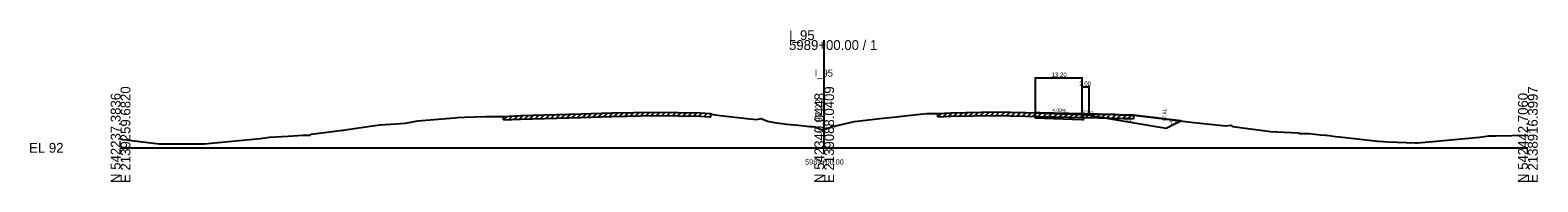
# Model space of a CAD drawing. Extents: x -12534 to 3403, y -1332 to 21983.
# Drawn here: x -25.7 to 402.8, y 17990.3 to 18033.5 of the extents above; entities that cross this region are included whole.
import ezdxf

# ---------------------------------------------------------------- set-up
doc = ezdxf.new("R2010")
doc.units = 0
for name, color, linetype in [('RD_GPK_XS_Cell', 7, 'Continuous'), ('RD_XD_TX_Width', 7, 'Continuous'), ('RD_XS_Base', 7, 'Continuous'), ('RD_XS_EarthShd', 7, 'Continuous'), ('RD_XS_EwShp', 7, 'Continuous'), ('RD_XS_ExGround', 7, 'Continuous'), ('RD_XS_ExPaveRet', 7, 'Continuous'), ('RD_XS_OSBase', 7, 'Continuous'), ('RD_XS_Pave', 7, 'Continuous'), ('RD_XS_TieSlope', 7, 'Continuous'), ('RD_XS_TX_Baseline', 7, 'Continuous'), ('RD_XS_TX_Elev_EX', 7, 'Continuous'), ('RD_XS_TX_Elev_PR', 7, 'Continuous'), ('RD_XS_TX_ShdSlope', 7, 'Continuous'), ('RD_XS_TX_Slope', 7, 'Continuous'), ('RD_XS_TX_Station', 7, 'Continuous')]:
    doc.layers.add(name, color=color, linetype=linetype)

msp = doc.modelspace()

# ---------------------------------------------------------------- linework, layer by layer
at = {"layer": 'RD_GPK_XS_Cell'}
for p, q in [((200, 18000), (200, 18030.63)), ((0, 18000), (200, 18000)), ((200, 18000), (400, 18000))]:
    msp.add_line(p, q, dxfattribs=at)
at = {"layer": 'RD_XD_TX_Width'}
for p, q in [((260, 18020.11), (260, 18010.16)), ((260, 18019.91), (273.2, 18019.91)), ((273.2, 18020.11), (273.2, 18009.63)), ((273.2, 18017.58), (273.2, 18009.63)), ((273.2, 18017.38), (275.2, 18017.38)), ((275.2, 18017.58), (275.2, 18009.47))]:
    msp.add_line(p, q, dxfattribs=at)
at = {"layer": 'RD_XS_Base'}
msp.add_line((260, 18008.56), (273.2, 18008.03), dxfattribs=at)
at = {"layer": 'RD_XS_EarthShd'}
msp.add_line((273.2, 18009.43), (275.2, 18009.27), dxfattribs=at)
at = {"layer": 'RD_XS_EwShp'}
msp.add_lwpolyline([(273.2, 18009.03), (273.2, 18009.43), (275.2, 18009.27), (297.2, 18005.61), (301.37, 18007.69), (297.29, 18008.18), (295.05, 18008.47), (294.33, 18008.54), (288.64, 18009.16), (287.91, 18009.27), (287.12, 18009.3), (286.84, 18009.33), (284.97, 18009.31), (282.59, 18009.43), (282.11, 18009.46), (265.41, 18009.82), (261.42, 18009.93), (260, 18009.96), (260, 18009.56), (260, 18008.56), (273.2, 18008.03), (273.7, 18008.01), (273.7, 18009.01)], close=True, dxfattribs=at)
at = {"layer": 'RD_XS_ExGround'}
msp.add_lwpolyline([(0, 18002.42), (10.99, 18001.15), (22.38, 18001.11), (23.19, 18001.1), (23.8, 18001.12), (39.73, 18002.62), (42.34, 18003.02), (47.63, 18003.35), (51.79, 18003.6), (53.86, 18003.6), (54.17, 18003.84), (63.19, 18004.97), (63.51, 18005.01), (64.49, 18005.16), (71.59, 18006.26), (73.83, 18006.56), (81.02, 18007.05), (84.49, 18007.67), (93.75, 18008.44), (95.02, 18008.55), (95.67, 18008.58), (97.75, 18008.67), (103.79, 18008.91), (107.63, 18008.91), (108.38, 18008.93), (108.85, 18008.94), (113.7, 18009.14), (130.84, 18009.65), (139.65, 18009.93), (152.01, 18010.16), (164.86, 18009.96), (167.33, 18009.77), (167.72, 18009.74), (168.08, 18009.53), (168.47, 18009.47), (170.39, 18009.23), (178.86, 18008.21), (180.79, 18008.02), (182.06, 18008.29), (183.26, 18007.83), (183.84, 18007.57), (185.86, 18007.23), (189.29, 18006.73), (192.69, 18006.39), (195.78, 18006.09), (196.54, 18006.08), (197.44, 18005.94), (199.01, 18005.21), (200, 18005.22), (201.6, 18005.82), (202.75, 18006.25), (202.76, 18006.08), (203.27, 18006.23), (208.47, 18007.49), (210.2, 18007.67), (215.84, 18008.29), (220.53, 18008.83), (222.91, 18009.1), (226.36, 18009.5), (229.16, 18009.73), (232.34, 18009.76), (235.95, 18009.99), (248.8, 18010.21), (261.42, 18009.93), (265.41, 18009.82), (282.11, 18009.46), (282.59, 18009.43), (284.97, 18009.31), (286.84, 18009.33), (287.12, 18009.3), (287.91, 18009.27), (288.64, 18009.16), (294.33, 18008.54), (295.05, 18008.47), (297.29, 18008.18), (305.07, 18007.24), (314.17, 18006.29), (315.54, 18006.45), (316.22, 18006.06), (318.85, 18005.69), (325.54, 18004.78), (326.88, 18004.66), (334.72, 18004.29), (335.31, 18004.07), (337.83, 18004.03), (341.11, 18003.64), (342.35, 18003.56), (342.91, 18003.59), (345.28, 18003.26), (346.47, 18003.11), (350.68, 18002.64), (357.39, 18001.86), (358.97, 18001.76), (360.25, 18001.69), (367.96, 18001.41), (368.65, 18001.39), (373.03, 18001.75), (386.21, 18003.02), (388.87, 18003.41), (391.03, 18003.4), (400, 18003.62)], dxfattribs=at)
at = {"layer": 'RD_XS_ExPaveRet'}
for p, q in [((108.85, 18007.94), (109.89, 18008.98)), ((108.85, 18007.94), (108.85, 18008.94)), ((108.85, 18007.94), (113.7, 18008.14)), ((110.35, 18008), (111.39, 18009.05)), ((111.85, 18008.07), (112.89, 18009.11)), ((113.35, 18008.13), (114.38, 18009.16)), ((113.7, 18008.14), (130.84, 18008.65)), ((114.85, 18008.18), (115.88, 18009.21)), ((116.35, 18008.22), (117.38, 18009.25)), ((117.85, 18008.27), (118.88, 18009.3)), ((119.35, 18008.31), (120.38, 18009.34)), ((120.85, 18008.35), (121.88, 18009.39)), ((122.35, 18008.4), (123.38, 18009.43)), ((123.85, 18008.44), (124.88, 18009.47)), ((125.35, 18008.49), (126.38, 18009.52)), ((126.85, 18008.53), (127.88, 18009.56)), ((128.35, 18008.58), (129.38, 18009.61)), ((129.85, 18008.62), (130.88, 18009.65)), ((130.84, 18008.65), (139.65, 18008.93)), ((131.35, 18008.67), (132.38, 18009.7)), ((132.85, 18008.71), (133.88, 18009.75)), ((134.35, 18008.76), (135.38, 18009.8)), ((135.85, 18008.81), (136.88, 18009.84)), ((137.35, 18008.86), (138.38, 18009.89)), ((138.85, 18008.91), (139.88, 18009.94)), ((139.65, 18008.93), (152.01, 18009.16)), ((140.35, 18008.95), (141.37, 18009.96)), ((141.85, 18008.97), (142.87, 18009.99)), ((143.35, 18009), (144.37, 18010.02)), ((144.85, 18009.03), (145.87, 18010.05)), ((146.35, 18009.06), (147.37, 18010.08)), ((147.85, 18009.08), (148.87, 18010.1)), ((149.35, 18009.11), (150.37, 18010.13)), ((150.85, 18009.14), (151.87, 18010.16)), ((152.01, 18009.16), (164.86, 18008.96)), ((152.35, 18009.16), (153.33, 18010.14)), ((153.85, 18009.13), (154.83, 18010.12)), ((155.35, 18009.11), (156.33, 18010.09)), ((156.85, 18009.08), (157.83, 18010.07)), ((158.35, 18009.06), (159.33, 18010.05)), ((159.85, 18009.04), (160.83, 18010.02)), ((161.35, 18009.01), (162.33, 18010)), ((162.85, 18008.99), (163.83, 18009.97)), ((164.35, 18008.97), (165.3, 18009.92)), ((164.86, 18008.96), (167.33, 18008.77)), ((165.85, 18008.88), (166.77, 18009.81)), ((167.33, 18008.77), (167.72, 18008.74)), ((167.72, 18009.74), (167.72, 18008.74)), ((232.34, 18008.76), (233.41, 18009.83)), ((232.34, 18008.76), (232.34, 18009.76)), ((232.34, 18008.76), (235.95, 18008.99)), ((233.84, 18008.85), (234.91, 18009.92)), ((235.34, 18008.95), (236.38, 18009.99)), ((235.95, 18008.99), (248.8, 18009.21)), ((236.84, 18009), (237.86, 18010.02)), ((238.34, 18009.03), (239.36, 18010.05)), ((239.84, 18009.05), (240.86, 18010.07)), ((241.34, 18009.08), (242.36, 18010.1)), ((242.84, 18009.11), (243.86, 18010.12)), ((244.34, 18009.13), (245.36, 18010.15)), ((245.84, 18009.16), (246.86, 18010.18)), ((247.34, 18009.18), (248.36, 18010.2)), ((248.8, 18009.21), (261.42, 18008.93)), ((248.84, 18009.21), (249.82, 18010.19)), ((250.34, 18009.18), (251.32, 18010.15)), ((251.84, 18009.14), (252.82, 18010.12)), ((253.34, 18009.11), (254.32, 18010.09)), ((254.84, 18009.08), (255.82, 18010.05)), ((256.34, 18009.04), (257.32, 18010.02)), ((257.84, 18009.01), (258.82, 18009.99)), ((259.34, 18008.98), (260.32, 18009.95)), ((260.84, 18008.94), (261.81, 18009.92)), ((261.42, 18008.93), (265.41, 18008.82)), ((262.34, 18008.91), (263.31, 18009.88)), ((263.84, 18008.86), (264.81, 18009.84)), ((265.34, 18008.82), (266.32, 18009.8)), ((265.41, 18008.82), (282.11, 18008.46)), ((266.84, 18008.79), (267.82, 18009.77)), ((268.34, 18008.76), (269.32, 18009.74)), ((269.84, 18008.72), (270.82, 18009.7)), ((271.34, 18008.69), (272.32, 18009.67)), ((272.84, 18008.66), (273.82, 18009.64)), ((274.34, 18008.63), (275.32, 18009.6)), ((275.84, 18008.59), (276.82, 18009.57)), ((277.34, 18008.56), (278.32, 18009.54)), ((278.84, 18008.53), (279.82, 18009.51)), ((280.34, 18008.49), (281.32, 18009.47)), ((281.84, 18008.46), (282.79, 18009.42)), ((282.11, 18008.46), (282.59, 18008.43)), ((282.59, 18008.43), (284.97, 18008.31)), ((283.34, 18008.39), (284.29, 18009.34)), ((284.84, 18008.31), (285.84, 18009.32)), ((284.97, 18008.31), (286.84, 18008.33)), ((286.34, 18008.33), (287.31, 18009.3)), ((286.84, 18008.33), (287.12, 18008.3)), ((287.12, 18008.3), (287.91, 18008.27)), ((287.91, 18009.27), (287.91, 18008.27))]:
    msp.add_line(p, q, dxfattribs=at)
at = {"layer": 'RD_XS_OSBase'}
for p, q in [((260, 18009.56), (260, 18009.96)), ((260, 18008.56), (260, 18009.56)), ((273.2, 18009.03), (273.2, 18009.43)), ((273.7, 18009.01), (273.2, 18009.03)), ((273.2, 18008.03), (273.7, 18008.01)), ((273.7, 18008.01), (273.7, 18009.01))]:
    msp.add_line(p, q, dxfattribs=at)
at = {"layer": 'RD_XS_Pave'}
msp.add_line((260, 18009.96), (273.2, 18009.43), dxfattribs=at)
at = {"layer": 'RD_XS_TieSlope'}
for p, q in [((275.2, 18009.27), (297.2, 18005.61)), ((297.2, 18005.61), (301.37, 18007.69))]:
    msp.add_line(p, q, dxfattribs=at)

# ---------------------------------------------------------------- texts
at = {"layer": 'RD_GPK_XS_Cell'}
for s, p in [('I_95', (190, 18030.63)), ('5989+00.00 / 1', (190, 18027.83)), ('EL 92', (-26, 17998.6))]:
    msp.add_text(s, height=2.8, dxfattribs=at).set_placement(p)
for s, p in [('E 2139259.6820', (2.8, 17990)), ('E 2139088.0409', (202.8, 17990)), ('E 2138916.3997', (402.8, 17990)), ('N 542237.3836', (0, 17990)), ('N 542340.0448', (200, 17990)), ('N 542442.7060', (400, 17990))]:
    msp.add_text(s, height=2.8, rotation=90, dxfattribs=at).set_placement(p)
at = {"layer": 'RD_XD_TX_Width'}
for s, p in [('13.20', (264.62, 18020.16)), ('2.00', (272.51, 18017.63))]:
    msp.add_text(s, height=1.25, dxfattribs=at).set_placement(p)
at = {"layer": 'RD_XS_TX_Baseline'}
msp.add_text('I_95', height=2, dxfattribs=at).set_placement((197.28, 18020.22))
at = {"layer": 'RD_XS_TX_Elev_EX'}
msp.add_text('97.22', height=2, rotation=90, dxfattribs=at).set_placement((199.5, 18007.22))
at = {"layer": 'RD_XS_TX_Elev_PR'}
msp.add_text('97.61', height=1, rotation=90, dxfattribs=at).set_placement((297.2, 18007.61))
at = {"layer": 'RD_XS_TX_ShdSlope'}
msp.add_text('12.5:1', height=1, rotation=355.4261, dxfattribs=at).set_placement((272.71, 18009.73))
msp.add_text('12.5:1', height=1, rotation=355.4261, dxfattribs=at).set_placement((272.71, 18009.73))
at = {"layer": 'RD_XS_TX_Slope'}
for s, rotation, p in [('4.00%', 357.7094, (264.82, 18010.27)), ('6:1', 350.5377, (285.55, 18007.8)), ('2:1', 26.5651, (298.5, 18006.54))]:
    msp.add_text(s, height=1, rotation=rotation, dxfattribs=at).set_placement(p)
at = {"layer": 'RD_XS_TX_Station'}
msp.add_text('5989+00.00', height=1.5, dxfattribs=at).set_placement((194.56, 17995.22))

doc.saveas('drawing.dxf')
